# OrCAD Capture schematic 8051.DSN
size B; title: PCB BOARD DESIGNING; rev: 0.1; note: VAR1
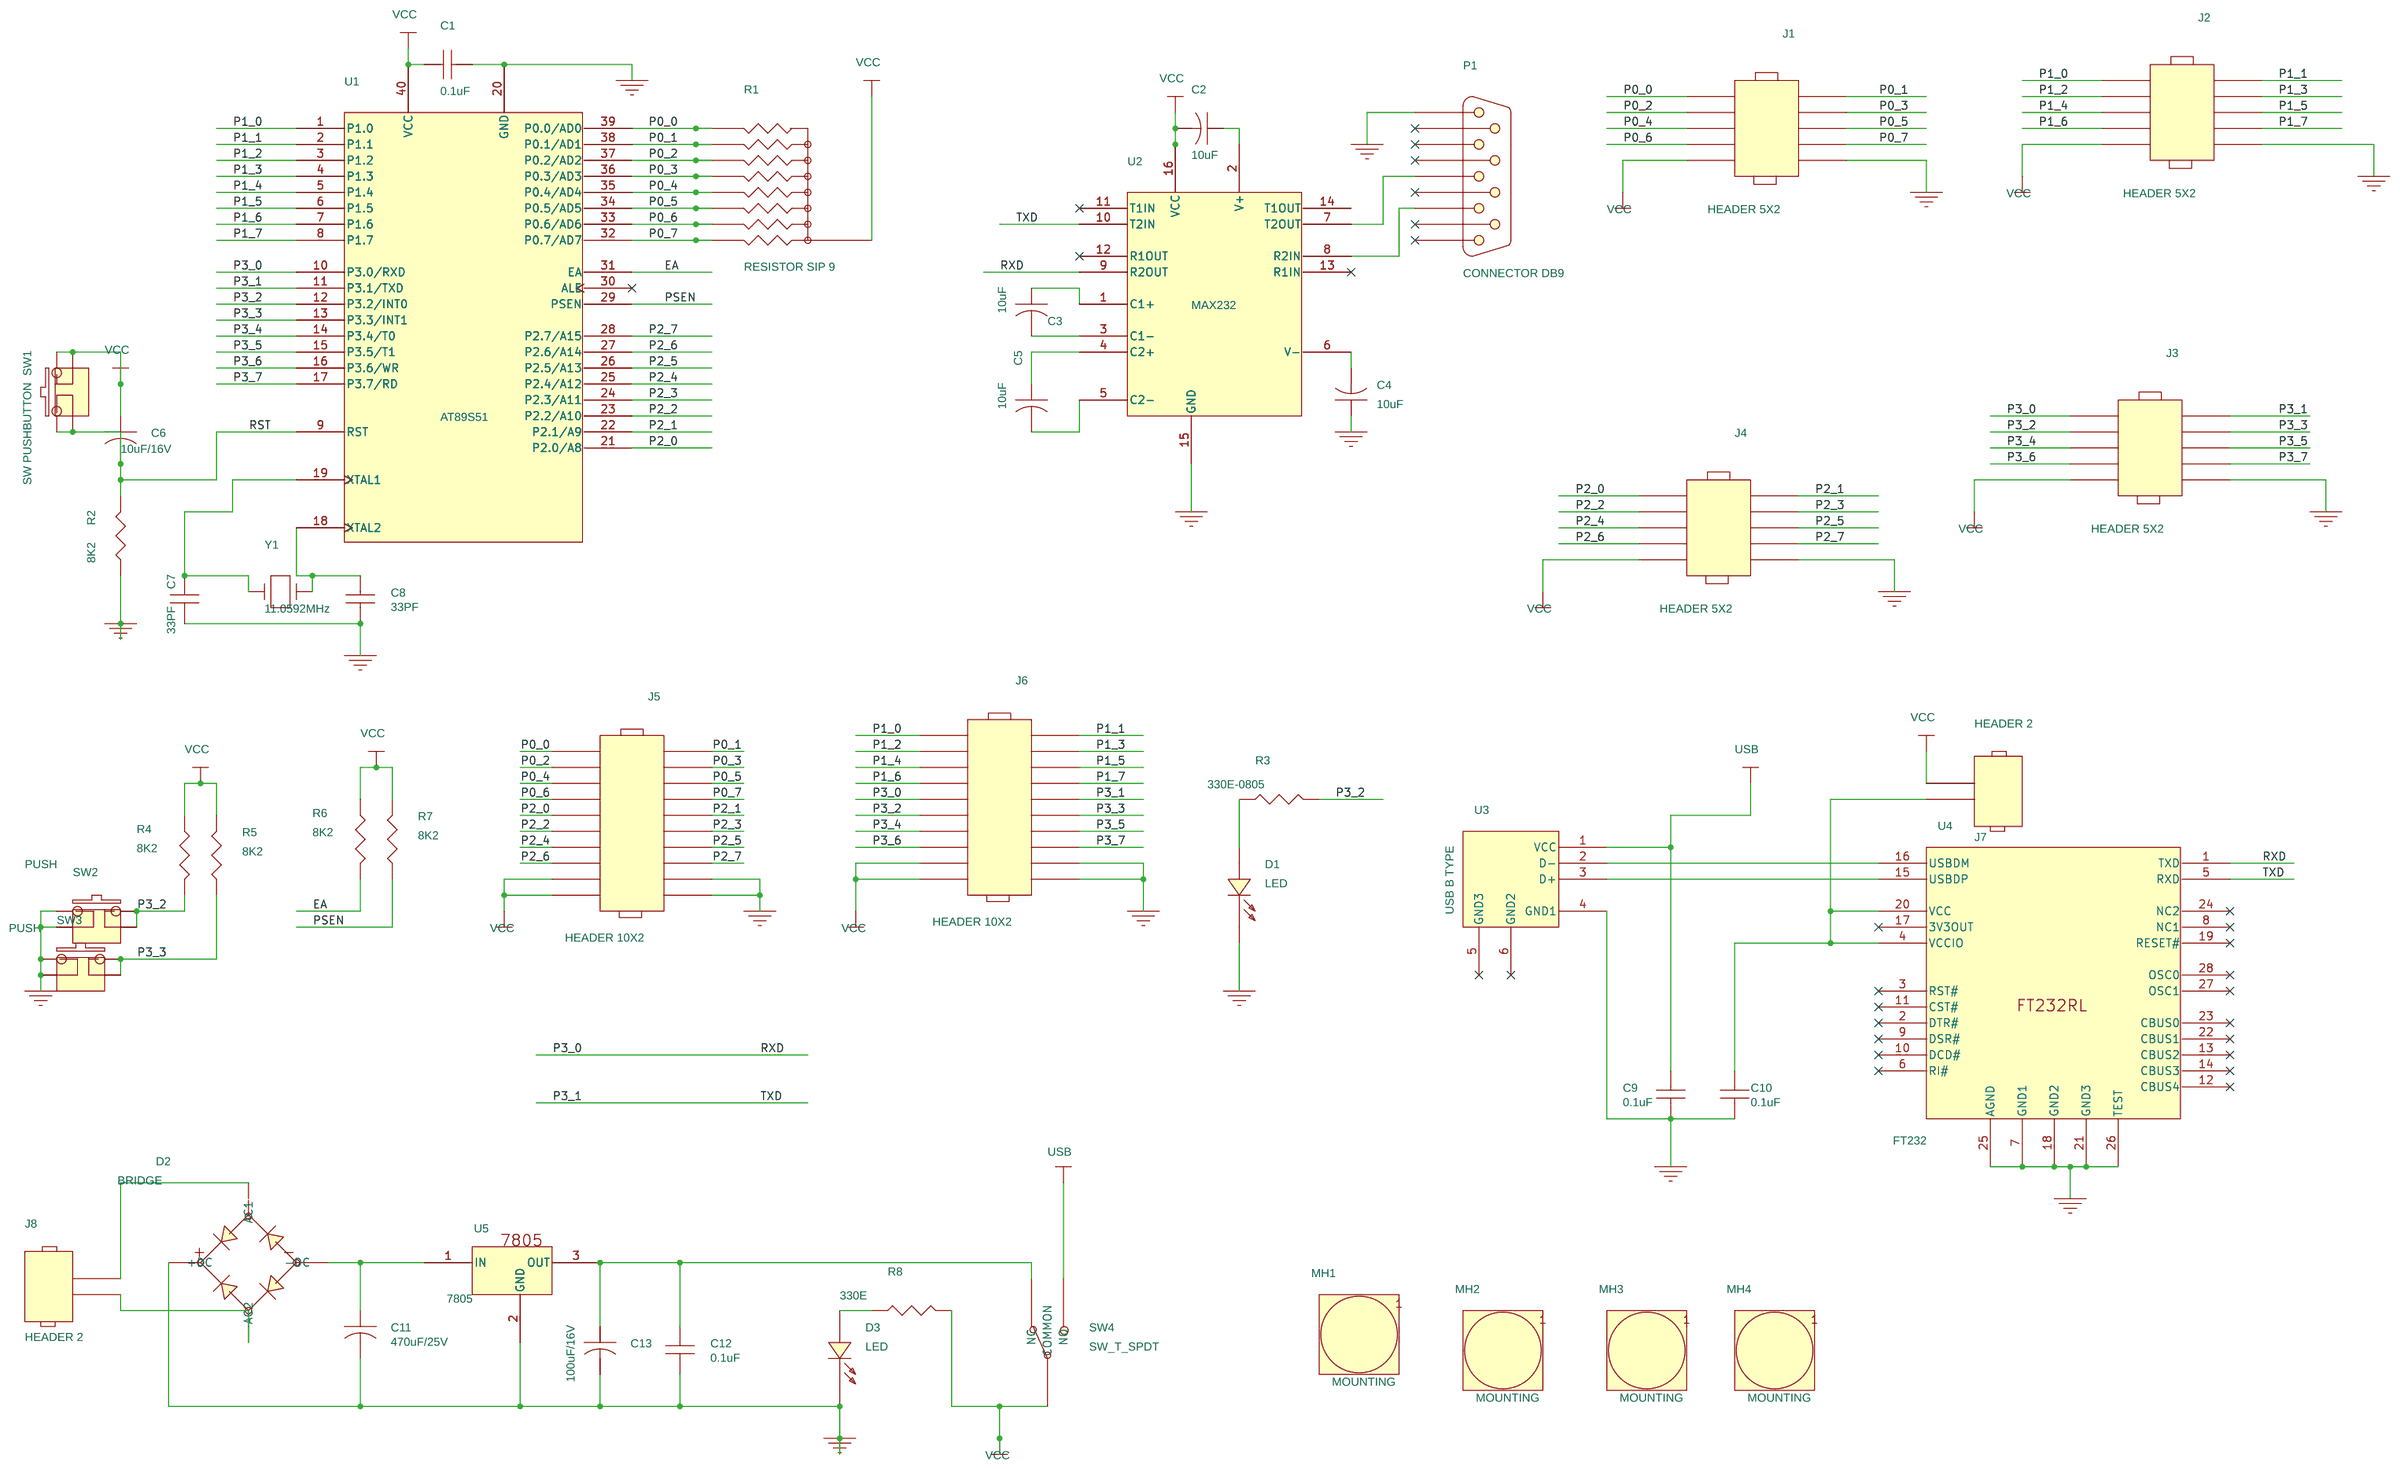
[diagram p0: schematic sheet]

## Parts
C1  0.1uF  [cap_disk_2p_252]
C2  10uF  [th_cap10uf]
C3  10uF  [th_cap10uf]
C4  10uF  [th_cap10uf]
C5  10uF  [th_cap10uf]
C6  10uF/16V  [th_cap10uf]
C7  33PF  [cap_disk_2p_252]
C8  33PF  [cap_disk_2p_252]
C9  0.1uF  [cap_disk_2p_252]
C10  0.1uF  [cap_disk_2p_252]
C11  470uF/25V  [cap470uf_]
C12  0.1uF  [cap_disk_2p_252]
C13  100uF/16V  [cap470uf_]
D1  LED  [LED_3mm]
D2  BRIDGE  [bridge_1A]
D3  LED  [LED_3mm]
J1  HEADER 5X2  [hdr_2x5p_254]
J2  HEADER 5X2  [hdr_2x5p_254]
J3  HEADER 5X2  [hdr_2x5p_254]
J4  HEADER 5X2  [hdr_2x5p_254]
J5  HEADER 10X2  [HDR_2X10P_254]
J6  HEADER 10X2  [HDR_2X10P_254]
J7  HEADER 2  [HDR_1X2P]
J8  HEADER 2  [HDR_1X2P]
MH1  MOUNTING  [mthole1]
MH2  MOUNTING  [mthole1]
MH3  MOUNTING  [mthole1]
MH4  MOUNTING  [mthole1]
P1  CONNECTOR DB9  [con_db9_RS]
R1  RESISTOR SIP 9  [res_sip]
R2  8K2  [resisitor_th]
R3  330E-0805  [resisitor_th]
R4  8K2  [resisitor_th]
R5  8K2  [resisitor_th]
R6  8K2  [resisitor_th]
R7  8K2  [resisitor_th]
R8  330E  [resisitor_th]
SW1  SW PUSHBUTTON  [push_button]
SW2  PUSH  [push_button]
SW3  PUSH  [push_button]
SW4  SW_T_SPDT  [slidesw]
U1  AT89S51  [89s52pinzifsocket]
U2  MAX232  [Base_dip_16p]
U3  USB B TYPE  [usb_4b_male]
U4  FT232  [SSOP_28P_065]
U5  7805  [78xx_3Pin]
Y1  11.0592MHz  [cry_25mh]

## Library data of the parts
C1 C7-C10 C12 = CAP_NP
C2-C6 C11 C13 = CAP
D1 D3 = LED
D2 = BRIDGE
J1-J4 = HEADER_5X2
J5 J6 = HEADER_10X2
J7 J8 = HEADER_2_4
MH1-MH4 = MOUNTING_0
P1 = CONNECTOR_DB9_0
R1 = RESISTOR_SIP_9
R2-R8 = R
SW1-SW3 = SW_PUSHBUTTON_0
SW4 = SW_T_SPDT
U1 = 8051_3
U2 = MAX232_5
U3 = USB_B_TYPE_0
U4 = FT232_0
U5 = 7805
Y1 = CRYSTAL

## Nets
GND: C1.2 C4.1 C7.2 C8.2 C9.2 C10.2 C11.2 C12.2 C13.2 D1.1(CATHODE) D2.4(+DC) D3.1(CATHODE) J1.10 J2.10 J3.10 J4.10 J5.18 J5.20 J6.18 J6.20 P1.5 R2.1 SW2.1 SW2.2 SW3.1 SW3.2 U1.20(GND) U2.15(GND) U3.4(GND1) U4.7(GND1) U4.18(GND2) U4.21(GND3) U4.25(AGND) U4.26(TEST) U5.2(GND)
VCC: C1.1 C2.2 C6.1 J1.9 J2.9 J3.9 J4.9 J5.17 J5.19 J6.17 J6.19 J7.1 R1.1 R4.1 R5.2 R6.1 R7.2 R8.2 SW1.3 SW1.4 SW4.2(COMMON) U1.40(VCC) U2.16(VCC)
EA: R6.2 U1.31(EA)
P0_0: J1.1 J5.1 R1.9 U1.39(P0.0/AD0)
P0_1: J1.2 J5.2 R1.8 U1.38(P0.1/AD1)
P0_2: J1.3 J5.3 R1.7 U1.37(P0.2/AD2)
P0_3: J1.4 J5.4 R1.6 U1.36(P0.3/AD3)
P0_4: J1.5 J5.5 R1.5 U1.35(P0.4/AD4)
P0_5: J1.6 J5.6 R1.4 U1.34(P0.5/AD5)
P0_6: J1.7 J5.7 R1.3 U1.33(P0.6/AD6)
P0_7: J1.8 J5.8 R1.2 U1.32(P0.7/AD7)
P1_0: J2.1 J6.1 U1.1(P1.0)
P1_1: J2.2 J6.2 U1.2(P1.1)
P1_2: J2.3 J6.3 U1.3(P1.2)
P1_3: J2.4 J6.4 U1.4(P1.3)
P1_4: J2.5 J6.5 U1.5(P1.4)
P1_5: J2.6 J6.6 U1.6(P1.5)
P1_6: J2.7 J6.7 U1.7(P1.6)
P1_7: J2.8 J6.8 U1.8(P1.7)
P2_0: J4.1 J5.9 U1.21(P2.0/A8)
P2_1: J4.2 J5.10 U1.22(P2.1/A9)
P2_2: J4.3 J5.11 U1.23(P2.2/A10)
P2_3: J4.4 J5.12 U1.24(P2.3/A11)
P2_4: J4.5 J5.13 U1.25(P2.4/A12)
P2_5: J4.6 J5.14 U1.26(P2.5/A13)
P2_6: J4.7 J5.15 U1.27(P2.6/A14)
P2_7: J4.8 J5.16 U1.28(P2.7/A15)
P3_0: J3.1 J6.9 U1.10(P3.0/RXD) U2.9(R2OUT) U4.1(TXD)
P3_1: J3.2 J6.10 U1.11(P3.1/TXD) U2.10(T2IN) U4.5(RXD)
P3_2: J3.3 J6.11 R3.2 R4.2 SW2.3 SW2.4 U1.12(P3.2/INT0)
P3_3: J3.4 J6.12 R5.1 SW3.3 SW3.4 U1.13(P3.3/INT1)
P3_4: J3.5 J6.13 U1.14(P3.4/T0)
P3_5: J3.6 J6.14 U1.15(P3.5/T1)
P3_6: J3.7 J6.15 U1.16(P3.6/WR)
P3_7: J3.8 J6.16 U1.17(P3.7/RD)
PSEN: R7.1 U1.29(PSEN)
RST: C6.2 R2.2 SW1.1 SW1.2 U1.9(RST)
USB: C9.1 SW4.3(NO) U3.1(VCC)
N00987: D2.1(AC1) J8.2
N00998: D2.3(AC2) J8.1
N01006: C11.1 D2.2(-DC) U5.1(IN)
N01109: C12.1 C13.1 SW4.1(NC) U5.3(OUT)
N01186: D3.2(ANODE) R8.1
N02523: C7.1 U1.19(XTAL1) Y1.1
N02580: C8.1 U1.18(XTAL2) Y1.2
N03974: C2.1 U2.2(V+)
N04033: C5.1 U2.4(C2+)
N04040: C5.2 U2.5(C2-)
N04047: C3.1 U2.1(C1+)
N04054: C3.2 U2.3(C1-)
N04276: C4.2 U2.6(V-)
N04539: P1.2 U2.8(R2IN)
N04549: P1.3 U2.7(T2OUT)
N07483: C10.1 J7.2 U4.4(VCCIO) U4.20(VCC)
N08493: U3.2(D-) U4.16(USBDM)
N08503: U3.3(D+) U4.15(USBDP)
N09228: D1.2(ANODE) R3.1

Not connected (* = marked no-connect by the designer): MH1 1; MH2 1; MH3 1; MH4 1; P1 1* 4* 6* 7* 8* 9* 10 11; U1 30(ALE)*; U2 11(T1IN)* 12(R1OUT)* 13(R1IN)* 14(T1OUT); U3 5(GND3)* 6(GND2)*; U4 2(DTR#)* 3(RST#)* 6(RI#)* 8(NC1)* 9(DSR#)* 10(DCD#)* 11(CST#)* 12(CBUS4)* 13(CBUS2)* 14(CBUS3)* 17(3V3OUT)* 19(RESET#)* 22(CBUS1)* 23(CBUS0)* 24(NC2)* 27(OSC1)* 28(OSC0)*
